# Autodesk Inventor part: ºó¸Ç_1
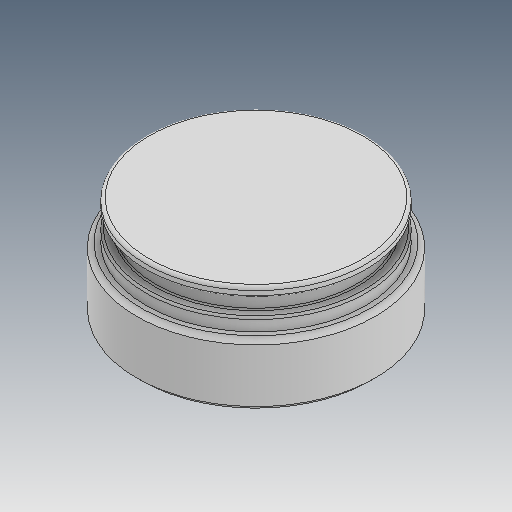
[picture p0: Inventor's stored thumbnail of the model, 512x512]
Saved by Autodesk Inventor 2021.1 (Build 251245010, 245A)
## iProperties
Created: 2019-04
Part Number: ºó¸Ç_1
Material: Ogólny
Document SubType Name: Modeling
Designer: user
Density: 1 g/cm^3
Appearance: Domyślna
Author: user
Revision Number: ÈÎºÎ
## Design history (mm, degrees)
feature "ÊäÈë1"
node "Bryła1"
